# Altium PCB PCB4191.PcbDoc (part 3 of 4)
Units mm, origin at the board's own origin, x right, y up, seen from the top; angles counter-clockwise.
Board outline 160 x 160 mm, 6 copper layers (Top Layer, IM1 RIS, IM2 Signal, IM3 Signal, IM4 GND, Bottom Layer), stack 1.582 mm thick; 143 components, 121 nets, 430 pads, 4983 vias.
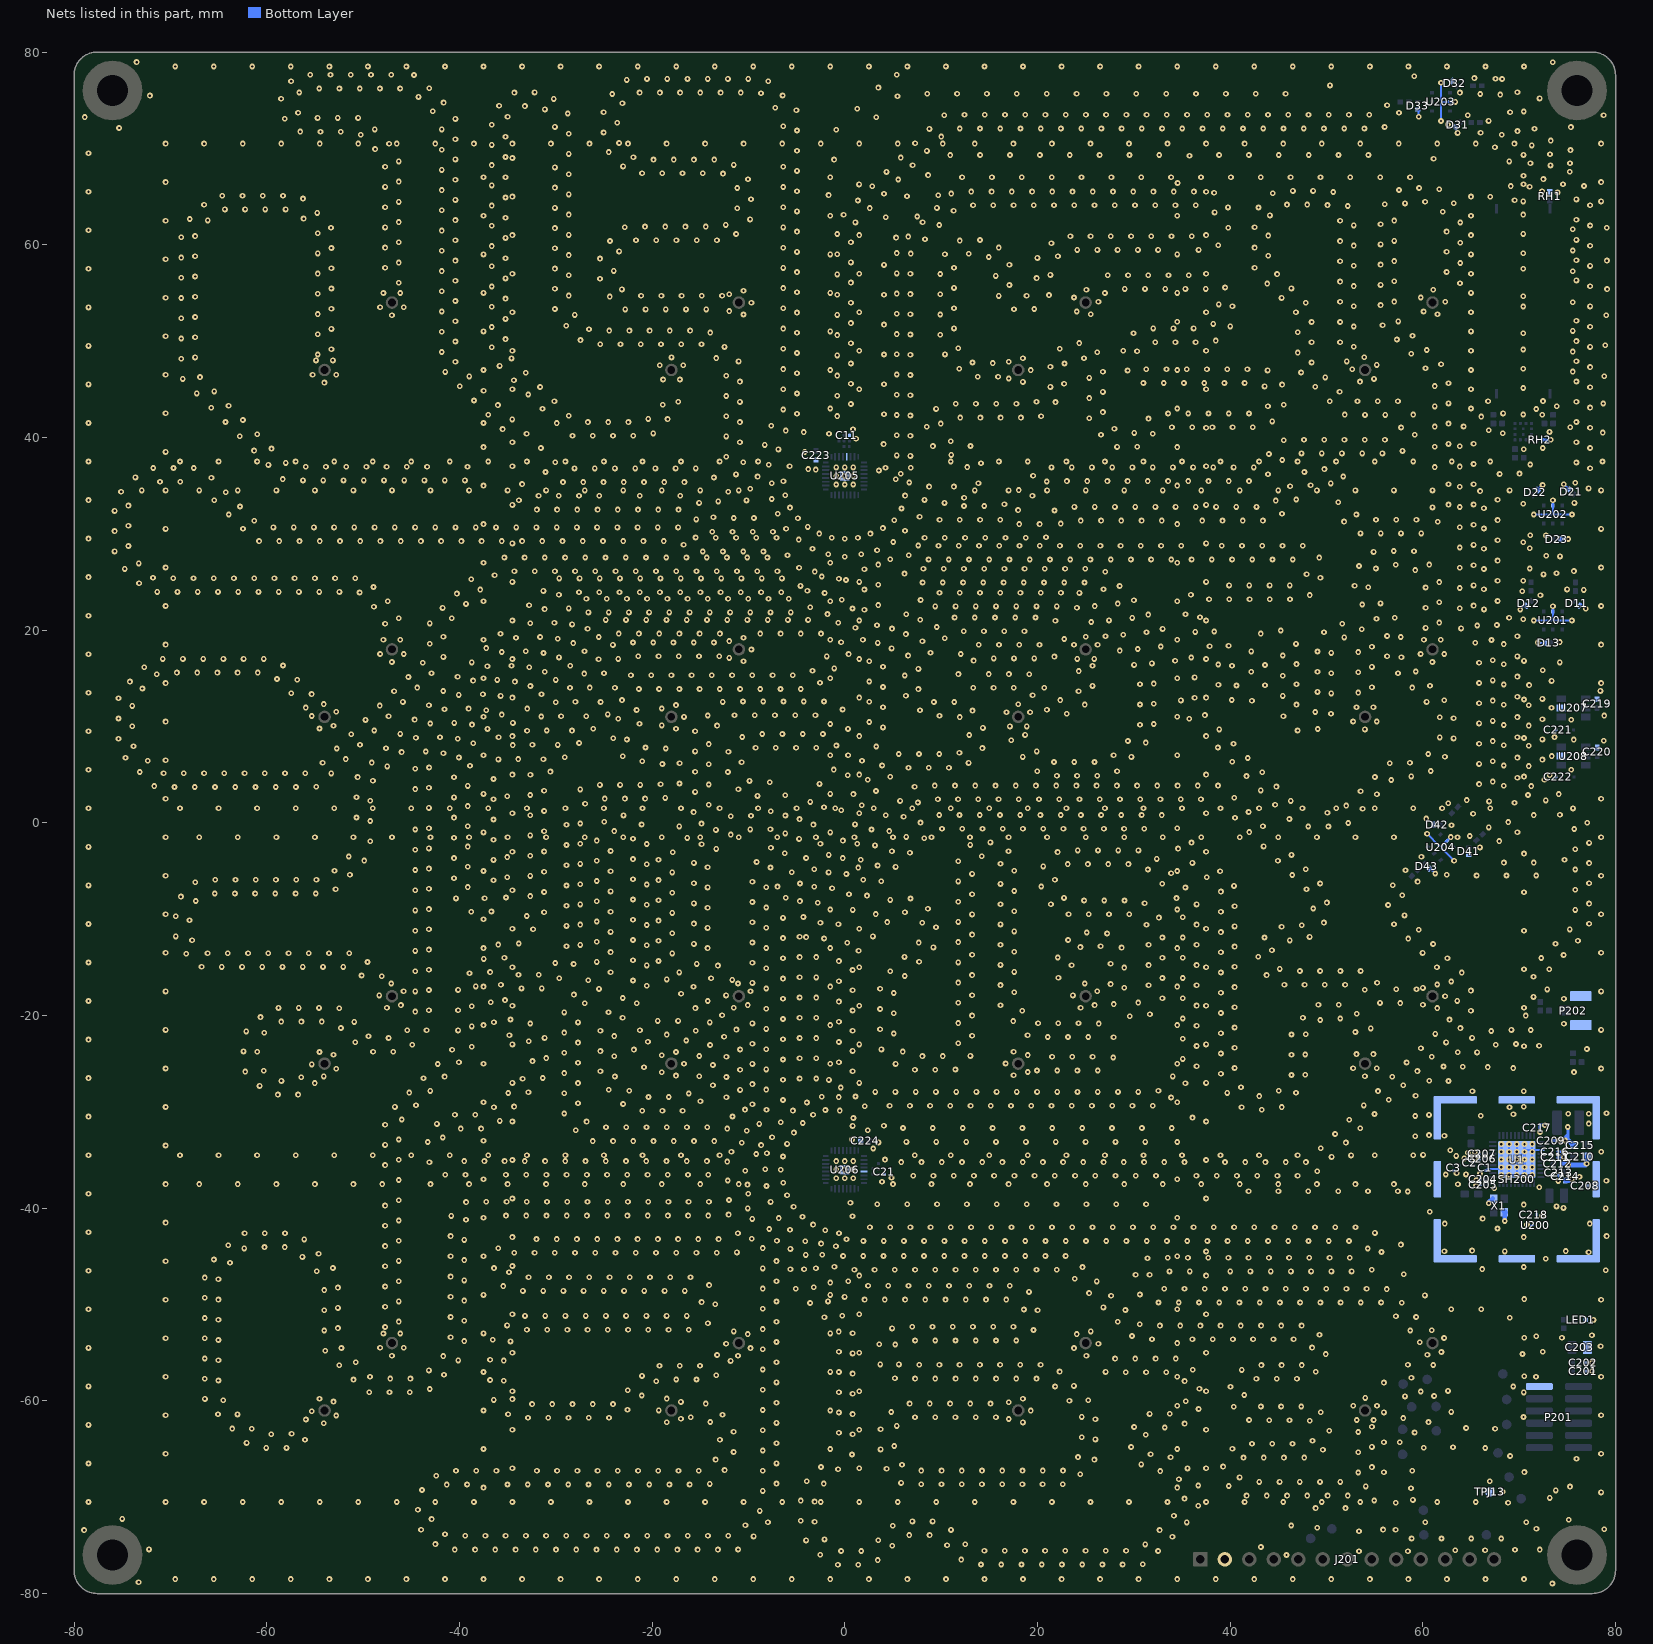
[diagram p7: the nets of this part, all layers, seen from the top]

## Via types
v1: diameter 0.6, hole 0.25, IM4 GND to Bottom Layer, tented bottom, 3953 vias
v2: diameter 0.6, hole 0.25, Top Layer to Bottom Layer, tented both sides, 851 vias
v3: diameter 0.6, hole 0.25, IM4 GND to Bottom Layer, tented both sides, 179 vias

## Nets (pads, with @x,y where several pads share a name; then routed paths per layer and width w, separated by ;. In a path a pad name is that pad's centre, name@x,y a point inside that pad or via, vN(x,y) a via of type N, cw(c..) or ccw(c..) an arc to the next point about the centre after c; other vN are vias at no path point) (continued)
GND: (continued)
  other v1: -0.714,-77.012 1.386,-77.012 14.137,-76.987 16.237,-76.987 18.337,-76.987 20.437,-76.987 22.537,-76.987 24.637,-76.987 26.737,-76.987 28.837,-76.987 30.937,-76.965 3.43,-76.528 12.099,-76.481 45.849,-76 -2.537,-75.97 58.449,-75.616 -0.388,-75.588 1.712,-75.588 32.521,-75.587 53.368,-75.606 14.494,-75.563 16.594,-75.563 18.694,-75.563 20.794,-75.563 22.894,-75.563 24.994,-75.563 27.094,-75.563 29.194,-75.563 63.363,-75.515 66.463,-75.515 -40.474,-75.437 -38.374,-75.437 -36.274,-75.437 -34.174,-75.437 -32.074,-75.437 -29.974,-75.437 -27.874,-75.437 -25.774,-75.437 -23.674,-75.437 -21.574,-75.437 -19.474,-75.437 -17.374,-75.437 -15.274,-75.437 -13.174,-75.437 69.562,-75.45 -11.074,-75.427 43.186,-75.174 4.915,-75.043 10.614,-74.996 31.188,-74.905 12.509,-74.877 -42.494,-74.863 -4.022,-74.486 3.483,-74.459 -2.109,-74.384 58.833,-74.286 61.933,-74.286 65.033,-74.286 68.133,-74.286 34.006,-74.102 -9.468,-74.075 -39.404,-74.013 -37.304,-74.013 -35.204,-74.013 -33.104,-74.013 -31.004,-74.013 -28.904,-74.013 -26.804,-74.013 -24.704,-74.013 -22.604,-74.013 -20.504,-74.013 -18.404,-74.013 -16.304,-74.013 -14.204,-74.013 -12.104,-74.013 6.7,-73.937 8.8,-73.937 -41.497,-73.845 53.375,-73.529 32.673,-73.42 -43.979,-73.378 11.024,-73.392 55.873,-73.366 71.783,-73.287 49.049,-73.166 4.968,-72.974 46.351,-72.941 -10.317,-72.91 35.491,-72.617 -7.983,-72.59 70.733,-72.597 -3.138,-72.553 7.017,-72.513 9.117,-72.513 -4.562,-72.456 -42.888,-72.272 34.158,-71.935 -8.832,-71.425 -44.312,-71.305 48.87,-71.135 51.97,-71.135 36.687,-70.891 -3.138,-70.453 -4.562,-70.356 54.966,-70.339 35.263,-70.149 41.709,-69.837 43.809,-69.837 45.909,-69.837 48.009,-69.837 50.109,-69.837 52.209,-69.837 -8.512,-69.349 -43.882,-69.249 58.768,-69.061 54.078,-68.88 39.86,-68.842 36.687,-68.791 -41.306,-68.689 -39.206,-68.687 -35.006,-68.687 -32.906,-68.687 -30.806,-68.687 -28.706,-68.687 -26.606,-68.687 -24.506,-68.687 -22.406,-68.687 -20.306,-68.687 -18.206,-68.687 -16.106,-68.687 7.934,-68.662 10.034,-68.662 12.134,-68.662 14.234,-68.662 16.334,-68.662 18.434,-68.662 20.534,-68.662 22.634,-68.662 -14.007,-68.623 -7.088,-68.59 -2.178,-68.585 5.839,-68.516 43.029,-68.413 45.129,-68.413 47.229,-68.413 49.329,-68.413 51.429,-68.413 -3.954,-68.346 34.675,-68.133 40.981,-67.949 -42.397,-67.765 24.45,-67.608 53.288,-67.435 55.96,-67.403 32.753,-67.287 -40.358,-67.263 -38.258,-67.263 -36.158,-67.263 -31.958,-67.263 -29.858,-67.263 -27.758,-67.263 -25.658,-67.263 -23.558,-67.263 -21.458,-67.263 -19.358,-67.263 -17.258,-67.263 -15.158,-67.263 -8.512,-67.249 7.946,-67.238 10.046,-67.238 12.146,-67.238 14.246,-67.238 16.346,-67.238 18.446,-67.238 20.546,-67.238 22.646,-67.238 -12.477,-67.185 -0.693,-67.101 4.339,-67.046 35.57,-67.013 54.712,-66.878 -2.469,-66.862 39.263,-66.829 5.936,-66.629 30.769,-66.601 -7.088,-66.49 -13.408,-66.101 25.908,-66.097 41.382,-65.887 43.482,-65.887 45.582,-65.887 47.682,-65.887 33.813,-65.863 24.208,-65.834 0.746,-65.571 31.736,-65.554 53.288,-65.335 -11.538,-65.306 -8.512,-65.149 49.622,-65.085 3.713,-65.042 40.229,-64.964 -60.053,-64.887 -57.953,-64.887 29.713,-64.786 54.712,-64.778 5.137,-64.687 42.268,-64.463 44.368,-64.463 46.468,-64.463 -7.088,-64.39 -62.088,-64.369 55.96,-64.303 48.544,-64.148 -56.032,-64.039 -12.962,-64.049 26.012,-63.999 24.588,-63.769 31.246,-63.512 0.812,-63.472 -59.524,-63.463 -57.424,-63.417 -0.612,-63.31 53.288,-63.235 -11.538,-63.206 50.287,-63.093 -8.512,-63.049 3.713,-62.942 -61.546,-62.897 -63.573,-62.884 33.207,-62.762 30.033,-62.71 54.712,-62.678 5.382,-62.601 35.269,-62.363 -54.082,-62.32 -7.088,-62.29 18.484,-62.237 -18.484,-62.213 -13.958,-62.2 48.26,-62.068 44.061,-62.012 46.161,-62.012 41.961,-61.99 53.137,-61.991 54.887,-61.991 -55.939,-61.932 26.012,-61.899 17.009,-61.887 -17.009,-61.863 -32.879,-61.762 -30.779,-61.762 -28.679,-61.762 -26.579,-61.762 -24.479,-61.762 -16,-61.712 7.284,-61.712 9.384,-61.712 11.484,-61.712 13.584,-61.712 15.684,-61.712 24.588,-61.669 -52.792,-61.524 -12.691,-61.452 -65.058,-61.399 -63.031,-61.412 -34.945,-61.387 0.812,-61.372 31.633,-61.351 33.733,-61.338 -0.612,-61.21 49.398,-61.191 55.96,-61.203 4.814,-61.154 -55.32,-61.082 19.309,-61.012 -19.309,-60.988 -22.55,-60.932 -8.512,-60.949 36.724,-60.849 40.378,-60.61 43.186,-60.588 45.286,-60.588 47.386,-60.588 52.787,-60.516 55.237,-60.516 -32.462,-60.338 -30.362,-60.338 -28.262,-60.338 -26.162,-60.338 -24.062,-60.338 -14.439,-60.288 6.727,-60.288 8.827,-60.288 10.927,-60.288 13.027,-60.288 15.127,-60.288 -7.088,-60.19 17.009,-60.137 -17.009,-60.113 -53.075,-60.075 35.388,-60.044 23.316,-59.998 -64.516,-59.927 25.268,-59.936 -36.43,-59.902 -34.497,-59.821 -66.422,-59.803 -54.524,-59.792 -18.484,-59.763 18.484,-59.787 54.012,-59.691 -21.065,-59.448 41.462,-59.389 0.812,-59.272 -49.357,-59.112 -47.257,-59.112 -45.157,-59.112 -0.612,-59.11 62.615,-58.966 -22.532,-58.899 -8.512,-58.849 -43.085,-58.768 36.812,-58.751 40.038,-58.538 21.831,-58.513 23.783,-58.451 -7.088,-58.09 55.96,-58.103 -19.58,-57.963 35.265,-57.948 -35.388,-57.919 -65.013,-57.886 -36.812,-57.837 -50.99,-57.792 -17.488,-57.787 -15.388,-57.787 42.727,-57.712 44.827,-57.712 46.927,-57.712 -66.437,-57.703 -47.19,-57.688 -45.09,-57.688 7.3,-57.687 9.4,-57.687 11.5,-57.687 13.6,-57.687 15.7,-57.687 17.8,-57.687 19.9,-57.687 5.2,-57.653 58.809,-57.613 -49.28,-57.487 -21.047,-57.414 -13.335,-57.343 -41.6,-57.283 0.812,-57.172 29.173,-57.037 31.273,-57.037 33.373,-57.037 -0.612,-57.01 27.074,-56.997 48.895,-56.978 22.298,-56.966 -43.17,-56.837 41.202,-56.79 36.105,-56.773 -8.512,-56.749 -19.229,-56.363 -17.129,-56.363 -15.029,-56.363 -52.475,-56.307 43.241,-56.288 45.341,-56.288 47.441,-56.288 7.719,-56.263 9.819,-56.263 11.919,-56.263 14.019,-56.263 16.119,-56.263 18.219,-56.263 20.319,-56.263 58.453,-56.26 61.069,-56.279 3.671,-56.213 5.62,-56.213 -50.765,-56.003 -7.088,-55.99 -11.85,-55.858 -35.388,-55.819 -65.013,-55.786 -40.115,-55.798 -36.812,-55.737 -66.437,-55.603 28.055,-55.613 30.155,-55.613 32.255,-55.613 34.355,-55.613 -41.685,-55.352 -11.082,-55.32 25.082,-55.32 -47.012,-55.309 -13.252,-55.244 60.476,-55.208 49.924,-55.147 0.812,-55.072 61.925,-54.925 -0.612,-54.91 -53.934,-54.797 -8.512,-54.649 -52.25,-54.518 -9.792,-54.524 23.792,-54.524 -48.237,-54.484 -45.787,-54.484 48.499,-54.474 5.234,-54.149 3.588,-54.115 -12.32,-54.082 26.32,-54.082 59.68,-53.918 -7.088,-53.89 -34.702,-53.834 -39.488,-53.794 7.293,-53.737 9.393,-53.737 11.493,-53.737 13.593,-53.737 15.693,-53.737 17.793,-53.737 -65.013,-53.686 -36.538,-53.655 31.884,-53.612 36.084,-53.612 38.184,-53.612 40.284,-53.612 42.384,-53.612 44.484,-53.612 46.584,-53.612 -66.437,-53.503 62.208,-53.476 74.438,-53.46 -40.912,-53.4 71.78,-53.303 29.812,-53.27 49.277,-53.149 -10.075,-53.075 24.075,-53.075 -47.887,-53.009 -46.137,-53.009 0.812,-52.972 -0.634,-52.81 -11.524,-52.792 25.524,-52.792 -54.037,-52.699 58.69,-52.697 60.918,-52.68 19.587,-52.645 -32.994,-52.612 -30.894,-52.612 -28.794,-52.612 -26.694,-52.612 -24.594,-52.612 -22.494,-52.612 -20.394,-52.612 -18.294,-52.612 -16.194,-52.612 -8.512,-52.549 4.907,-52.481 -52.613,-52.449 -47.712,-52.334 7,-52.313 9.1,-52.313 11.2,-52.313 13.3,-52.313 15.4,-52.313 17.5,-52.313 -35.053,-52.17 32.71,-52.188 34.81,-52.188 36.91,-52.188 39.01,-52.188 41.11,-52.188 43.21,-52.188 45.31,-52.188 47.41,-52.188 30.614,-52.057 -14.205,-51.938 -7.088,-51.79 -46.288,-51.777 28.327,-51.785 -39.488,-51.694 -65.013,-51.586 -66.437,-51.403 69.031,-51.378 -2.119,-51.325 -40.912,-51.3 59.303,-51.296 57.205,-51.212 -33.197,-51.188 -31.097,-51.188 -28.997,-51.188 -26.897,-51.188 -24.797,-51.188 -22.697,-51.188 -20.597,-51.188 -18.497,-51.188 -16.397,-51.188 -0.261,-51.168 -54.037,-50.599 20.012,-50.589 29.129,-50.572 18.588,-50.516 62.958,-50.498 66.058,-50.498 -8.512,-50.449 -52.613,-50.349 26.842,-50.3 -47.712,-50.234 -13.438,-49.983 -3.604,-49.84 57.818,-49.811 32.562,-49.787 34.662,-49.787 36.762,-49.787 38.862,-49.787 40.962,-49.787 43.062,-49.787 45.162,-49.787 47.262,-49.787 49.362,-49.787 51.462,-49.787 53.562,-49.787 55.662,-49.787 -14.862,-49.754 -7.088,-49.69 -1.746,-49.683 -46.288,-49.677 -39.488,-49.594 -65.013,-49.486 2.057,-49.487 4.157,-49.487 6.257,-49.487 8.357,-49.487 10.457,-49.487 12.557,-49.487 14.657,-49.487 16.757,-49.487 -66.437,-49.303 -40.912,-49.2 -0.024,-49.208 27.644,-49.087 60.212,-49.06 30.631,-48.963 25.357,-48.815 19.12,-48.688 -33.408,-48.587 -31.308,-48.587 -29.208,-48.587 -27.108,-48.587 -25.008,-48.587 -22.908,-48.587 -20.808,-48.587 -18.708,-48.587 -16.608,-48.587 -54.037,-48.499 56.263,-48.4 33.163,-48.363 35.263,-48.363 37.363,-48.363 39.463,-48.363 41.563,-48.363 43.663,-48.363 45.763,-48.363 47.863,-48.363 49.963,-48.363 52.063,-48.363 54.163,-48.363 -8.512,-48.349 -5.089,-48.355 -52.613,-48.249 -3.231,-48.198 -47.712,-48.134 -35.447,-48.085 2.415,-48.063 4.515,-48.063 6.615,-48.063 8.715,-48.063 10.815,-48.063 12.915,-48.063 15.015,-48.063 17.115,-48.063 -14.083,-47.984 -1.509,-47.723 26.159,-47.602 -46.288,-47.577 -7.088,-47.59 0.37,-47.588 -39.488,-47.494 -65.013,-47.386 23.873,-47.33 -66.437,-47.203 -32.816,-47.163 -30.716,-47.163 -28.616,-47.163 -26.516,-47.163 -24.416,-47.163 -22.316,-47.163 -20.216,-47.163 -18.116,-47.163 -16.016,-47.163 -40.912,-47.1 30.188,-46.91 31.636,-46.922 58.02,-46.868 -34.855,-46.662 33.705,-46.562 35.805,-46.562 40.005,-46.562 42.105,-46.562 44.205,-46.562 46.305,-46.562 48.405,-46.562 50.505,-46.562 52.605,-46.562 -54.811,-46.547 0.996,-46.387 3.096,-46.387 5.196,-46.387 7.296,-46.387 9.396,-46.387 11.496,-46.387 13.596,-46.387 15.696,-46.387 17.796,-46.387 19.896,-46.387 21.996,-46.387 54.698,-46.391 -5.649,-46.331 -4.224,-46.347 -8.512,-46.249 -2.994,-46.238 -53.129,-46.214 -36.412,-46.22 24.674,-46.117 -1.081,-46.076 -47.712,-46.034 -63.809,-45.666 -7.088,-45.49 -46.288,-45.477 -39.488,-45.394 -65.487,-45.33 72.752,-45.249 31.418,-45.208 33.517,-45.138 35.617,-45.138 37.717,-45.138 39.817,-45.138 41.917,-45.138 44.017,-45.138 46.117,-45.138 48.217,-45.138 50.317,-45.138 52.417,-45.138 -56.295,-45.062 -40.912,-45 -0.18,-44.963 1.92,-44.963 4.02,-44.963 6.12,-44.963 8.22,-44.963 10.32,-44.963 12.42,-44.963 14.52,-44.963 16.62,-44.963 18.72,-44.963 20.82,-44.963 22.92,-44.963 -4.05,-44.85 -2.35,-44.825 -54.614,-44.729 -34.3,-44.637 -32.2,-44.637 -30.1,-44.637 -28,-44.637 -25.9,-44.637 -23.8,-44.637 -21.7,-44.637 -19.6,-44.637 -17.5,-44.637 -15.4,-44.637 -13.3,-44.637 -11.2,-44.595 55.712,-44.553 -5.649,-44.231 -62.324,-44.181 -35.973,-44.166 54.288,-44.184 -8.512,-44.149 -60.229,-44.037 -58.129,-44.037 -0.925,-43.95 -47.712,-43.934 -64.002,-43.845 57.727,-43.782 1.935,-43.412 4.035,-43.412 6.135,-43.412 8.235,-43.412 10.335,-43.412 12.435,-43.412 14.535,-43.412 16.635,-43.412 18.735,-43.412 20.835,-43.412 22.935,-43.412 25.035,-43.412 27.135,-43.412 29.235,-43.412 31.335,-43.412 33.435,-43.412 35.535,-43.412 37.635,-43.412 39.735,-43.412 41.835,-43.412 43.935,-43.412 46.035,-43.412 48.135,-43.412 50.235,-43.412 52.335,-43.412 -7.046,-43.391 -46.288,-43.377 -39.488,-43.294 -56.099,-43.244 -32.002,-43.213 -29.902,-43.213 -27.802,-43.213 -25.702,-43.213 -23.602,-43.213 -21.502,-43.213 -19.402,-43.213 -17.302,-43.213 -15.202,-43.213 -13.102,-43.213 0.175,-43.225 -9.655,-43.173 -40.912,-42.9 -62.302,-42.613 -60.202,-42.613 -58.102,-42.613 -11.094,-42.598 55.025,-42.568 -7.832,-42.162 67.747,-42.114 2.607,-41.988 4.707,-41.988 6.807,-41.988 8.907,-41.988 11.007,-41.988 13.107,-41.988 15.207,-41.988 17.307,-41.988 19.407,-41.988 21.507,-41.988 23.607,-41.988 25.707,-41.988 27.807,-41.988 29.907,-41.988 32.007,-41.988 34.107,-41.988 36.207,-41.988 38.307,-41.988 40.407,-41.988 42.507,-41.988 44.607,-41.988 46.707,-41.988 48.807,-41.988 50.907,-41.988 53.007,-41.988 -47.712,-41.834 -46.288,-41.277 -39.318,-41.201 -9.609,-41.113 -40.845,-40.801 -35.163,-40.768 -33.063,-40.768 -30.963,-40.768 -28.863,-40.768 -26.763,-40.768 -24.663,-40.768 -22.563,-40.768 -20.463,-40.768 -18.363,-40.768 -16.263,-40.768 -14.163,-40.768 -12.066,-40.669 60.716,-40.361 -10.068,-40.021 -47.712,-39.734 3.378,-39.594 6.478,-39.594 9.578,-39.594 12.678,-39.594 15.778,-39.594 18.878,-39.594 21.978,-39.594 25.078,-39.594 28.178,-39.594 31.278,-39.594 -39.309,-39.369 -37.209,-39.344 -35.109,-39.344 -33.009,-39.344 -30.909,-39.344 -28.809,-39.344 -26.709,-39.344 -24.609,-39.344 -22.509,-39.344 -20.409,-39.344 -18.309,-39.344 -16.209,-39.344 -14.109,-39.344 -46.288,-39.177 -12.017,-39.156 -10.02,-38.507 58.43,-38.267 41.911,-38.246 45.011,-38.246 48.111,-38.246 51.211,-38.246 54.311,-38.246 57.411,-38.246 -10.1,-37.549 -12.157,-37.126 -46.288,-37.077 7.101,-36.644 9.201,-36.644 11.301,-36.644 13.401,-36.644 15.501,-36.644 17.601,-36.644 19.701,-36.644 21.801,-36.644 23.901,-36.644 26.001,-36.644 28.101,-36.644 30.201,-36.644 32.301,-36.644 36.501,-36.644 38.601,-36.644 40.701,-36.644 42.801,-36.644 44.901,-36.644 47.001,-36.644 -41.473,-36.537 -39.373,-36.537 -35.173,-36.537 -33.073,-36.537 -30.973,-36.537 -28.873,-36.537 -26.773,-36.537 -24.673,-36.537 -22.573,-36.537 -20.473,-36.537 -18.373,-36.537 -16.273,-36.537 -14.173,-36.537 49.045,-36.162 -10.342,-36.124 -47.712,-35.534 -43.113,-35.227 5.862,-35.219 7.962,-35.219 10.062,-35.219 12.162,-35.219 14.262,-35.219 16.362,-35.219 18.462,-35.219 20.562,-35.219 22.662,-35.219 24.762,-35.219 26.862,-35.219 28.962,-35.219 31.062,-35.219 33.162,-35.219 35.262,-35.219 39.462,-35.219 41.562,-35.219 43.662,-35.219 45.762,-35.219 47.862,-35.219 -12.21,-35.166 -39.51,-35.113 -37.41,-35.113 -35.31,-35.113 -33.21,-35.113 -31.11,-35.113 -29.01,-35.113 -26.91,-35.113 -24.81,-35.113 -22.71,-35.113 -20.61,-35.113 -18.51,-35.113 -16.41,-35.113 -14.31,-35.113 -46.288,-34.977 50.53,-34.677 60.022,-34.476 -11.767,-34.141 49.401,-33.791 -8.685,-33.458 -47.712,-33.434 -10.686,-33.207 3.5,-33.175 52.015,-33.193 -43.287,-33.134 6.396,-33.123 9.496,-33.123 12.596,-33.123 15.696,-33.123 18.796,-33.123 21.896,-33.123 24.996,-33.123 28.096,-33.123 31.196,-33.123 -26.154,-33.037 -24.054,-33.037 -21.954,-33.037 -19.854,-33.037 -17.754,-33.037 -15.654,-33.037 -13.554,-33.037 -46.288,-32.877 -41.736,-32.668 59.215,-32.538 60.639,-32.415 50.886,-32.306 -10.17,-31.973 -27.924,-31.908 2.391,-31.917 -39.853,-31.737 -37.753,-31.737 -12.19,-31.742 53.5,-31.708 6.038,-31.677 9.138,-31.677 12.238,-31.677 15.338,-31.677 18.438,-31.677 21.538,-31.677 24.638,-31.677 27.738,-31.677 30.838,-31.677 33.938,-31.677 -24.786,-31.613 -22.686,-31.613 -20.586,-31.613 -18.486,-31.613 -16.386,-31.613 -14.286,-31.613 4.06,-31.447 -47.712,-31.334 -42.341,-31.259 -8.875,-31.254 -26.8,-31.018 -35.81,-30.942 52.371,-30.821 -45.991,-30.798 0.89,-30.643 36.09,-30.595 -11.655,-30.488 59.215,-30.438 66.011,-30.408 -40.467,-30.313 -38.367,-30.313 60.639,-30.315 54.985,-30.223 -29.112,-30.177 -21.033,-29.887 -18.933,-29.887 -16.833,-29.887 -8.126,-29.795 -10.36,-29.769 43.269,-29.787 -36.416,-29.534 41.187,-29.519 -46.701,-29.494 45.351,-29.507 -34.325,-29.457 4.654,-29.362 6.754,-29.362 8.854,-29.362 10.954,-29.362 13.054,-29.362 15.154,-29.362 17.254,-29.362 19.354,-29.362 21.454,-29.362 23.554,-29.362 25.654,-29.362 27.754,-29.362 29.854,-29.362 31.954,-29.362 53.856,-29.337 -44.506,-29.313 -9.587,-29.223 -23.015,-29.192 -27.688,-29.114 -14.984,-28.892 -6.413,-28.769 56.47,-28.738 33.873,-28.509 -12.287,-28.486 -20.373,-28.463 -18.273,-28.463 1.111,-28.407 43.014,-28.363 59.251,-28.338 -58.844,-28.212 -56.744,-28.212 -16.205,-28.097 -29.112,-28.077 -34.931,-28.049 39.702,-28.034 46.836,-28.022 -45.216,-28.009 -32.84,-27.972 3.158,-27.938 5.258,-27.938 7.358,-27.938 9.458,-27.938 11.558,-27.938 13.658,-27.938 15.758,-27.938 17.858,-27.938 19.958,-27.938 22.058,-27.938 24.158,-27.938 26.258,-27.938 28.358,-27.938 30.458,-27.938 65.141,-27.87 55.341,-27.852 -43.021,-27.828 -22.372,-27.821 32.554,-27.813 45.039,-27.804 -24.5,-27.707 -10.863,-27.73 -8.163,-27.695 -0.424,-27.479 41.126,-27.444 -60.743,-27.314 57.955,-27.253 -13.688,-27.24 -9.587,-27.123 -55.014,-27.022 35.358,-27.024 -27.688,-27.014 62.658,-26.799 -58.481,-26.788 60.661,-26.782 -6.413,-26.669 -1.645,-26.686 -33.447,-26.564 -2.962,-26.544 -43.731,-26.524 -4.687,-26.537 -31.355,-26.487 -56.416,-26.408 -12.287,-26.386 56.826,-26.367 -41.536,-26.343 -23.857,-26.336 -54.082,-26.32 34.039,-26.329 -15.112,-26.304 53.988,-26.309 -17.516,-26.237 17.516,-26.213 46.363,-26.174 47.787,-26.15 39.038,-26.042 -29.112,-25.977 -18.991,-25.887 75.686,-25.879 18.991,-25.863 -62.223,-25.825 -25.362,-25.793 0.812,-25.782 59.439,-25.768 -60.302,-25.741 19.947,-25.712 22.047,-25.712 24.147,-25.712 26.247,-25.712 -10.863,-25.63 7.28,-25.637 9.38,-25.637 11.48,-25.607 -8.163,-25.595 -52.792,-25.524 52.763,-25.484 55.213,-25.484 40.462,-25.451 69.39,-25.458 -20.843,-25.364 66.726,-25.36 62.146,-25.297 64.143,-25.315 36.512,-25.27 -13.688,-25.14 -55.32,-25.082 -42.246,-25.039 -9.587,-25.023 5.27,-25.028 -16.691,-25.012 16.691,-24.988 -27.688,-24.914 58.311,-24.882 -40.051,-24.858 -0.612,-24.857 -32.412,-24.737 -6.413,-24.569 35.088,-24.509 -4.687,-24.437 -2.962,-24.444 -30.988,-24.42 27.856,-24.363 -12.287,-24.286 21.517,-24.288 23.617,-24.288 25.717,-24.288 60.924,-24.283 -23.938,-24.237 -15.112,-24.204 8.059,-24.213 10.159,-24.213 13.039,-24.2 -18.991,-24.137 18.991,-24.113 -53.075,-24.075 46.363,-24.074 47.787,-24.05 53.113,-24.009 54.863,-24.009 39.038,-23.942 -29.112,-23.877 65.628,-23.83 63.631,-23.812 -54.524,-23.792 -17.516,-23.787 -60.988,-23.756 -48.962,-23.762 -46.862,-23.762 6.01,-23.752 17.516,-23.763 -62.412,-23.733 -25.362,-23.693 0.812,-23.682 -40.761,-23.554 -21.887,-23.542 -10.863,-23.53 3.803,-23.526 -8.163,-23.495 59.796,-23.397 40.462,-23.351 -38.715,-23.238 36.512,-23.17 -13.982,-23.061 67.573,-23.037 -44.895,-23.027 69.671,-22.958 -9.587,-22.923 11.788,-22.887 -27.688,-22.814 -50.821,-22.786 62.409,-22.798 -0.612,-22.757 -20.44,-22.722 -32.808,-22.674 -16.462,-22.595 -6.413,-22.469 35.088,-22.409 -47.35,-22.338 -31.159,-22.327 -4.687,-22.337 -2.962,-22.344 65.116,-22.327 27.905,-22.264 21.064,-22.237 23.164,-22.237 25.264,-22.237 -12.532,-22.2 -49.442,-22.151 -23.938,-22.137 13.212,-22.107 -34.815,-22.054 18.971,-22.062 -18.472,-21.987 46.363,-21.974 47.856,-21.951 61.281,-21.912 5.087,-21.866 39.038,-21.842 -60.256,-21.788 -29.112,-21.777 53.003,-21.71 -62.134,-21.652 67.091,-21.613 -25.362,-21.593 -15.467,-21.576 0.812,-21.582 -43.41,-21.542 -40.137,-21.549 -21.268,-21.535 -45.412,-21.529 69.188,-21.498 71.191,-21.509 -11.252,-21.466 3.663,-21.431 -8.163,-21.395 54.599,-21.339 63.894,-21.313 -52.306,-21.301 40.462,-21.251 -38.713,-21.138 36.512,-21.07 -32.638,-20.835 -9.587,-20.823 26.361,-20.84 20.061,-20.813 22.161,-20.813 24.261,-20.813 11.788,-20.787 -36.425,-20.707 -27.688,-20.714 -14.017,-20.715 -50.927,-20.666 -0.612,-20.657 -58.499,-20.637 -56.399,-20.637 -54.299,-20.637 17.478,-20.585 -19.407,-20.563 -17.307,-20.563 49.341,-20.466 -34.697,-20.421 62.766,-20.427 -6.413,-20.369 35.088,-20.309 51.436,-20.312 -2.962,-20.244 47.551,-20.242 -23.068,-20.226 -4.687,-20.237 -60.649,-20.167 29.58,-20.087 70.672,-20.013 13.212,-20.007 -12.737,-19.981 31.668,-19.864 53.138,-19.831 5.087,-19.766 39.038,-19.742 -29.112,-19.677 -24.524,-19.667 -44.587,-19.598 18.415,-19.508 64.987,-19.52 0.812,-19.482 -43.163,-19.457 -40.137,-19.449 3.663,-19.331 -8.163,-19.295 -52.479,-19.252 -15.502,-19.23 61.484,-19.237 -58.779,-19.213 -56.679,-19.213 -54.579,-19.213 -47.524,-19.208 -11.524,-19.208 24.476,-19.208 40.462,-19.151 -38.713,-19.038 36.512,-18.97 16.163,-18.948 -46.075,-18.925 -10.075,-18.925 25.925,-18.925 49.162,-18.895 51.262,-18.888 60.009,-18.887 27.909,-18.816 -21.583,-18.741 -26.998,-18.731 55.555,-18.693 57.655,-18.712 11.788,-18.687 30.45,-18.663 -36.737,-18.63 -0.612,-18.557 -14.221,-18.496 63.563,-18.484 -35.268,-18.4 -6.413,-18.269 32.962,-18.21 35.088,-18.209 -23.04,-18.182 -4.687,-18.137 -2.962,-18.144 71.483,-18.075 62.309,-18.012 -48.32,-17.918 -12.32,-17.918 13.212,-17.907 23.68,-17.918 -28.112,-17.83 -16.987,-17.745 5.087,-17.666 39.038,-17.642 17.587,-17.578 -44.587,-17.498 -45.792,-17.476 -9.792,-17.476 26.208,-17.476 64.987,-17.42 0.812,-17.382 -43.163,-17.357 -40.137,-17.349 53.965,-17.322 72.908,-17.294 57.238,-17.288 59.338,-17.288 -25.513,-17.246 3.663,-17.231 -8.163,-17.195 -33.554,-17.187 -31.454,-17.187 29.012,-17.132 60.009,-17.137 40.462,-17.051 -15.706,-17.011 -38.297,-16.979 -20.563,-16.906 31.538,-16.866 36.512,-16.87 16.163,-16.848 45.627,-16.812 47.727,-16.812 49.827,-16.812 51.927,-16.812 -35.692,-16.809 61.484,-16.787 27.588,-16.741 -47.082,-16.68 -11.082,-16.68 24.918,-16.68 -9.587,-16.623 11.788,-16.587 55.255,-16.597 -0.612,-16.457 62.945,-16.477 -21.987,-16.365 -26.627,-16.345 -11.689,-16.304 -18.472,-16.26 -6.413,-16.169 -29.633,-16.141 -13.877,-16.13 32.962,-16.11 35.088,-16.109 22.171,-16.078 -4.687,-16.037 -2.962,-16.044 71.483,-15.975 -48.059,-15.934 6.229,-15.903 -50.157,-15.85 13.212,-15.807 43.781,-15.813 -33.871,-15.763 -31.771,-15.763 -38.949,-15.617 39.038,-15.542 64.032,-15.55 -24.313,-15.523 -17.191,-15.526 -36.812,-15.495 17.587,-15.478 -44.587,-15.398 4.708,-15.409 47.238,-15.388 49.338,-15.388 51.438,-15.388 53.538,-15.388 0.812,-15.282 -43.163,-15.257 73.127,-15.206 45.15,-15.167 -8.163,-15.095 29.012,-15.032 61.46,-14.992 -64.661,-14.962 -62.561,-14.962 -60.461,-14.962 -58.361,-14.962 -56.261,-14.962 -54.161,-14.962 -52.061,-14.962 -66.76,-14.95 40.462,-14.951 -20.563,-14.806 -13.174,-14.819 23.537,-14.789 31.538,-14.766 36.512,-14.77 16.163,-14.748 -28.148,-14.656 -15.362,-14.645 27.588,-14.641 -30.057,-14.549 -9.587,-14.523 11.788,-14.487 -49.544,-14.449 -25.737,-14.443 7.714,-14.418 -19.337,-14.347 -0.612,-14.357 -21.987,-14.265 -37.464,-14.132 -6.413,-14.069 62.547,-14.065 72.284,-14.034 -35.327,-14.01 32.962,-14.01 35.088,-14.009 22.113,-13.979 -2.962,-13.944 -4.687,-13.937 6.193,-13.924 42.913,-13.901 74.612,-13.721 13.212,-13.707 -68.364,-13.594 -66.136,-13.538 -64.036,-13.538 -61.936,-13.538 -59.836,-13.538 -57.736,-13.538 -55.636,-13.538 -53.536,-13.538 -51.436,-13.538 -17.913,-13.554 59.975,-13.507 39.038,-13.442 -24.313,-13.423 17.587,-13.378 -44.587,-13.298 1.432,-13.275 44.337,-13.231 -43.163,-13.157 -14.238,-13.008 -8.163,-12.995 28.733,-12.951 9.199,-12.934 24.457,-12.901 40.462,-12.851 -28.887,-12.805 26.555,-12.812 -20.563,-12.706 -27.463,-12.671 36.512,-12.67 -35.98,-12.647 16.163,-12.648 31.538,-12.666 61.062,-12.58 -15.662,-12.567 73.769,-12.549 -33.842,-12.525 0.25,-12.443 -9.587,-12.423 7.678,-12.44 11.788,-12.387 -25.737,-12.343 -19.337,-12.247 76.097,-12.236 -67.749,-12.193 46.174,-12.212 -21.987,-12.165 23.175,-12.167 58.49,-12.022 -2.15,-12.008 -6.413,-11.969 32.962,-11.91 35.088,-11.909 43.564,-11.904 -4.018,-11.861 -4.687,-11.837 48.241,-11.842 -69.437,-11.789 2.917,-11.79 13.212,-11.607 27.223,-11.492 -17.913,-11.454 25.125,-11.388 39.038,-11.342 -24.313,-11.323 17.587,-11.278 -44.587,-11.198 59.577,-11.095 -43.163,-11.057 75.254,-11.064 -32.357,-11.04 -14.238,-10.908 -8.163,-10.895 9.462,-10.85 45.342,-10.788 40.462,-10.751 -28.887,-10.705 47.437,-10.631 -20.563,-10.606 -27.463,-10.571 31.32,-10.577 36.512,-10.57 16.163,-10.548 57.005,-10.537 -0.665,-10.523 -15.662,-10.467 77.253,-10.483 -2.533,-10.376 8.038,-10.371 49.726,-10.357 -9.587,-10.323 4.402,-10.305 11.788,-10.287 -25.737,-10.243 -19.337,-10.147 -68.013,-10.11 -21.987,-10.065 -6.413,-9.869 32.599,-9.842 35.088,-9.809 -4.292,-9.774 -69.437,-9.689 -33.01,-9.677 58.092,-9.61 13.212,-9.507 3.22,-9.473 23.225,-9.487 25.325,-9.487 27.425,-9.487 29.525,-9.487 -17.913,-9.354 -31.213,-9.279 6.239,-9.287 39.038,-9.242 -38.776,-9.237 -24.313,-9.223 -36.677,-9.206 17.587,-9.178 -44.587,-9.098 0.82,-9.038 75.829,-9.044 -43.163,-8.957 8.63,-8.922 48.613,-8.891 -14.238,-8.808 -8.163,-8.795 40.462,-8.651 -28.887,-8.605 56.388,-8.53 -20.563,-8.506 -27.463,-8.471 21.397,-8.454 36.512,-8.47 16.163,-8.448 77.253,-8.383 -15.662,-8.367 31.114,-8.357 -2.807,-8.289 50.037,-8.28 -9.587,-8.223 11.788,-8.187 -25.737,-8.143 -4.656,-8.124 -67.357,-8.115 24.835,-8.063 26.935,-8.063 29.035,-8.063 -19.337,-8.047 4.721,-8.004 -21.987,-7.965 -40.355,-7.852 6.817,-7.863 -37.392,-7.838 22.752,-7.795 34.432,-7.814 -6.131,-7.788 -35.161,-7.752 -68.913,-7.656 -32.637,-7.611 2.304,-7.553 57.862,-7.523 0.437,-7.406 13.212,-7.407 -65.407,-7.337 -63.307,-7.337 -61.207,-7.337 -59.107,-7.337 -57.007,-7.337 -54.907,-7.337 -17.913,-7.254 -31.213,-7.179 39.038,-7.142 -24.313,-7.123 17.587,-7.078 -44.587,-6.998 75.829,-6.944 47.925,-6.907 -52.855,-6.889 -43.163,-6.857 -1.322,-6.804 -14.238,-6.708 35.352,-6.72 -8.163,-6.695 -39.138,-6.67 -6.983,-6.625 -3.171,-6.639 20.388,-6.613 40.396,-6.553 -28.887,-6.505 56.881,-6.489 -20.563,-6.406 -27.463,-6.371 16.163,-6.348 32.947,-6.329 -4.646,-6.303 49.334,-6.301 77.253,-6.283 -15.662,-6.267 -67.428,-6.171 -9.587,-6.123 59.45,-6.1 3.789,-6.068 11.788,-6.087 -25.737,-6.043 -36.462,-5.955 -19.337,-5.947 1.922,-5.921 21.812,-5.917 -65.344,-5.913 -63.244,-5.913 -61.144,-5.913 -59.044,-5.913 -56.944,-5.913 -54.844,-5.913 -21.987,-5.865 -40.562,-5.762 -35.038,-5.655 37.564,-5.646 -32.637,-5.511 65.581,-5.469 68.681,-5.469 71.781,-5.469 46.44,-5.422 -51.37,-5.404 62.482,-5.384 0.163,-5.319 13.212,-5.307 33.867,-5.235 -17.913,-5.154 -1.686,-5.154 -5.498,-5.14 -31.213,-5.079 -24.313,-5.023 38.956,-5.024 -52.962,-4.981 17.587,-4.978 58.2,-4.925 -44.587,-4.898 31.462,-4.844 75.829,-4.844 -3.161,-4.819 47.849,-4.816 -43.163,-4.757 -7.712,-4.644 -14.238,-4.608 -39.138,-4.57 5.274,-4.583 20.595,-4.523 3.407,-4.436 -28.887,-4.405 -20.563,-4.306 -27.463,-4.271 23.137,-4.287 25.237,-4.287 27.337,-4.287 29.437,-4.287 16.163,-4.248 -15.662,-4.167 36.079,-4.161 77.253,-4.183 68.417,-4.131 71.517,-4.131 -9.151,-4.069 11.788,-3.987 -25.737,-3.943 44.955,-3.937 -49.885,-3.919 -36.462,-3.855 -19.337,-3.847 1.648,-3.835 74.701,-3.843 -21.987,-3.765 32.382,-3.75 -40.562,-3.662 -4.013,-3.656 -0.201,-3.669 -35.038,-3.555 59.851,-3.519 -51.477,-3.496 14.215,-3.462 -32.637,-3.411 -1.676,-3.334 46.364,-3.332 -6.227,-3.159 6.759,-3.098 -17.848,-3.055 22.087,-3.044 -31.213,-2.979 4.892,-2.951 16.996,-2.963 -24.313,-2.923 24.179,-2.863 26.279,-2.863 28.379,-2.863 30.479,-2.863 -44.587,-2.798 75.829,-2.744 -13.332,-2.714 34.594,-2.676 -43.163,-2.657 -7.667,-2.584 65.925,-2.55 -39.138,-2.47 43.47,-2.452 3.133,-2.35 -28.887,-2.305 13.026,-2.291 -20.563,-2.206 -14.859,-2.227 1.284,-2.184 -27.463,-2.171 -2.528,-2.171 77.253,-2.083 35.986,-2.054 15.111,-2.038 -49.263,-1.913 67.924,-1.901 -25.737,-1.843 -0.191,-1.849 -36.462,-1.755 -4.742,-1.674 -21.987,-1.665 8.244,-1.613 -16.363,-1.57 -40.562,-1.562 6.376,-1.466 64.875,-1.375 -32.637,-1.311 -11.847,-1.229 -6.182,-1.099 69.817,-0.991 41.985,-0.968 -31.213,-0.879 4.618,-0.865 -23.926,-0.859 -13.374,-0.742 -44.587,-0.698 -9.818,-0.687 2.769,-0.699 -7.718,-0.661 75.715,-0.647 10.09,-0.612 12.19,-0.612 14.29,-0.612 16.39,-0.612 18.49,-0.612 20.59,-0.612 22.69,-0.612 24.79,-0.612 26.89,-0.612 28.99,-0.612 31.09,-0.612 -43.163,-0.557 34.501,-0.569 66.839,-0.477 48.098,-0.387 50.198,-0.387 -39.138,-0.37 -17.18,-0.372 43.394,-0.362 -28.887,-0.205 -21.094,-0.174 -3.257,-0.189 1.062,-0.164 -14.878,-0.085 -27.463,-0.071 52.265,-0.017 7.861,0.019 77.064,0.008 68.866,0.073 -24.97,0.112 -49.263,0.187 -36.462,0.345 -4.697,0.386 46.149,0.394 -40.562,0.538 40.5,0.517 -50.687,0.55 6.103,0.62 -11.834,0.686 -9.735,0.737 -22.974,0.762 -6.166,0.754 -32.637,0.789 4.254,0.786 9.806,0.812 11.906,0.812 14.006,0.812 16.106,0.812 18.206,0.812 20.306,0.812 22.406,0.812 24.506,0.812 26.606,0.812 28.706,0.812 30.806,0.812 32.906,0.796 74.23,0.837 65.215,0.928 50.09,1.037 -15.695,1.112 41.909,1.123 -7.686,1.197 -31.213,1.221 -0.362,1.301 53.75,1.468 75.584,1.498 -43.163,1.543 -2.163,1.603 -39.138,1.73 52.053,1.785 1.752,1.82 -14.113,1.87 44.664,1.879 -26.951,1.966 69.513,2.071 7.588,2.105 -3.587,2.169 66.873,2.216 -49.263,2.287 5.739,2.271 46.289,2.268 72.745,2.322 64.554,2.352 9.661,2.438 11.761,2.438 13.861,2.438 15.961,2.438 18.061,2.438 20.161,2.438 22.261,2.438 24.361,2.438 26.461,2.438 28.561,2.438 30.661,2.438 32.761,2.438 34.861,2.438 36.961,2.438 -36.462,2.445 -24.924,2.513 -22.824,2.513 -20.724,2.513 -18.625,2.58 40.424,2.608 -40.562,2.638 -50.687,2.65 -35.038,2.745 -9.056,2.788 -6.188,2.854 -32.637,2.889 70.915,2.885 55.235,2.953 0.898,2.981 74.099,2.983 -15.537,3.207 53.538,3.27 3.237,3.305 -31.213,3.321 43.179,3.364 -27.466,3.466 -11.038,3.481 -44.587,3.502 -43.163,3.643 -69.571,3.713 -67.471,3.713 -65.371,3.713 -63.271,3.713 -61.171,3.713 -59.071,3.713 -56.971,3.713 -54.871,3.738 7.244,3.735 44.804,3.753 -71.668,3.814 71.26,3.807 -39.138,3.83 9.34,3.862 11.44,3.862 13.54,3.862 15.64,3.862 17.74,3.862 19.84,3.862 21.94,3.862 24.04,3.862 26.14,3.862 28.24,3.862 30.34,3.862 32.44,3.862 34.54,3.862 36.64,3.862 38.74,3.862 68.398,3.85 -25.419,3.937 -23.319,3.937 -21.219,3.937 -14.113,3.97 -19.121,4.012 65.838,4.015 -2.623,4.034 -17.157,4.082 -7.791,4.21 67.262,4.28 -9.886,4.344 -48.976,4.367 56.72,4.438 2.383,4.465 72.614,4.468 -36.462,4.545 69.812,4.672 -50.567,4.747 -40.562,4.738 55.022,4.755 4.722,4.789 58.786,4.813 41.694,4.849 22.014,4.888 24.114,4.888 26.214,4.888 0.302,4.945 -32.629,4.989 -53.293,5.124 -70.703,5.137 -68.603,5.137 -66.503,5.137 -64.403,5.137 -62.303,5.137 -60.203,5.137 -58.103,5.137 -56.003,5.137 43.319,5.238 -73.18,5.272 -12.137,5.271 -15.537,5.307 -30.553,5.315 19.966,5.352 28.261,5.354 60.809,5.377 -1.138,5.519 -44.587,5.602 6.608,5.713 8.708,5.713 10.808,5.713 -43.15,5.743 -47.491,5.852 70.988,5.89 -38.901,5.917 3.868,5.95 68.388,5.95 -14.113,6.07 -18.936,6.103 65.838,6.115 -17.149,6.182 56.561,6.184 -54.207,6.226 12.847,6.215 58.66,6.237 -49.104,6.253 -10.713,6.274 21.717,6.312 23.817,6.312 25.917,6.312 40.209,6.333 67.262,6.38 -21.016,6.388 1.787,6.43 -72.342,6.45 -35.951,6.582 72.412,6.558 -31.282,6.6 -51.808,6.609 -33.905,6.613 41.834,6.723 -74.664,6.757 -40.056,6.776 69.812,6.772 -29.068,6.799 18.481,6.837 29.746,6.839 62.294,6.862 -23.049,6.916 0.347,7.004 27.899,7.006 5.6,7.137 7.7,7.137 9.8,7.137 60.557,7.139 -41.665,7.228 11.896,7.278 -46.006,7.337 -12.082,7.37 -43.506,7.402 -15.537,7.407 19.925,7.407 -52.722,7.711 -18.586,7.713 -47.619,7.738 14.28,7.75 -9.257,7.788 -7.157,7.788 -5.057,7.788 -2.957,7.788 -20.683,7.812 38.724,7.818 3.272,7.915 -73.827,7.934 70.988,7.99 -0.87,8.023 68.388,8.05 -34.466,8.067 -50.323,8.094 -32.42,8.098 -29.797,8.085 -14.113,8.17 40.349,8.208 65.838,8.215 -38.572,8.261 -27.583,8.284 31.231,8.324 67.262,8.48 29.384,8.491 17.288,8.565 -22.613,8.642 72.412,8.658 -40.18,8.713 -75.387,8.729 63.187,8.762 -24.037,8.769 -44.521,8.822 61.763,8.858 -42.021,8.887 -35.931,8.887 69.812,8.872 -10.651,8.907 12.913,9.115 18.712,9.122 -51.237,9.196 -46.134,9.223 -8.573,9.212 -6.473,9.212 -4.373,9.212 -2.273,9.212 -15.537,9.507 -32.981,9.552 -48.838,9.579 -28.312,9.57 47.003,9.579 -30.935,9.583 38.864,9.693 53.988,9.691 -37.087,9.746 0.337,9.741 49.097,9.739 -26.098,9.769 -17.516,9.763 -54.524,9.792 14.337,9.849 3.962,9.898 17.137,10.009 18.887,10.009 -73.963,10.03 -53.075,10.075 -13.255,10.087 -18.991,10.113 70.988,10.089 68.388,10.15 30.638,10.176 -38.695,10.198 32.062,10.253 -21.309,10.288 -43.036,10.307 65.838,10.315 -40.536,10.372 -34.446,10.371 2.538,10.467 52.763,10.516 55.213,10.516 67.262,10.58 -49.752,10.68 -44.649,10.708 72.412,10.758 35.754,10.788 -23.506,10.801 -75.387,10.829 63.187,10.862 11.924,10.968 61.763,10.958 69.812,10.972 -16.691,10.988 -31.496,11.037 -47.354,11.064 -29.45,11.068 -26.827,11.055 45.523,11.069 -55.32,11.082 9.829,11.113 -14.217,11.14 -11.452,11.163 -9.352,11.163 -7.252,11.163 -5.152,11.163 -3.052,11.163 37.379,11.178 -35.602,11.231 -24.613,11.254 23.029,11.313 50.468,11.329 16.787,11.484 19.237,11.484 48.838,11.495 -52.792,11.524 13.257,11.65 -37.21,11.683 7.809,11.684 -21.614,11.712 -0.23,11.763 20.974,11.744 -41.551,11.792 -39.051,11.857 -32.961,11.856 -18.991,11.863 -55.96,11.953 53.113,11.991 54.863,11.991 3.962,11.998 -73.963,12.13 -48.267,12.165 -43.164,12.193 70.988,12.189 -17.516,12.213 24.9,12.267 68.388,12.25 30.638,12.276 46.887,12.273 -54.082,12.32 18.012,12.309 32.062,12.353 65.838,12.415 -30.011,12.522 -45.869,12.549 -25.342,12.54 -12.661,12.55 9.254,12.537 11.354,12.537 60.393,12.55 -27.965,12.553 2.538,12.567 -10.562,12.587 -8.462,12.587 -6.362,12.587 -4.262,12.587 -2.162,12.587 42.255,12.672 34.888,12.701 67.262,12.68 62.227,12.73 -23.128,12.739 22.372,12.737 40.157,12.748 72.412,12.858 -75.387,12.929 36.312,12.987 69.812,13.072 -35.725,13.167 45.463,13.168 6.343,13.188 19.489,13.229 -40.066,13.277 -55.347,13.354 -37.566,13.342 -31.476,13.341 -57.445,13.438 50.487,13.429 53.288,13.519 49.063,13.583 -46.782,13.65 24.265,13.647 -41.68,13.678 -21.37,13.888 -19.27,13.888 -17.17,13.888 -15.07,13.888 -12.97,13.888 -10.87,13.888 -8.77,13.888 -6.67,13.888 -4.57,13.888 7.637,13.878 -72.901,13.942 -28.526,14.006 -23.858,14.025 13.341,14.024 15.441,14.013 17.541,14.013 20.71,14.022 -44.384,14.034 -26.48,14.037 58.908,14.035 54.712,14.076 3.962,14.098 -32.632,14.2 25.712,14.204 60.742,14.215 40.657,14.25 43.612,14.275 71.03,14.289 38.781,14.334 68.388,14.35 30.638,14.376 46.887,14.373 32.062,14.453 65.838,14.515 -2.575,14.543 -74.198,14.659 -34.24,14.652 2.538,14.667 73.363,14.731 -38.581,14.762 67.262,14.78 -36.081,14.826 -29.991,14.826 -56.832,14.839 -58.93,14.923 36.312,15.087 -45.297,15.135 -40.195,15.163 69.812,15.172 45.463,15.268 6.213,15.284 -22.199,15.312 -20.099,15.312 -17.999,15.312 -15.899,15.312 -13.799,15.312 -11.699,15.312 -9.599,15.312 -7.499,15.312 -5.399,15.312 19.135,15.41 -71.416,15.427 11.789,15.439 14.935,15.437 17.035,15.437 -27.041,15.491 -42.899,15.519 -24.995,15.522 57.423,15.52 50.487,15.529 -69.322,15.588 -67.222,15.588 -65.122,15.588 -63.022,15.588 -60.922,15.588 53.288,15.619 -31.147,15.685 42.188,15.688 49.063,15.683 59.258,15.7 24.288,15.747 -3.352,15.781 72.452,15.835 7.637,15.978 -1.09,16.027 -72.713,16.144 -32.755,16.137 54.712,16.176 3.962,16.198 -37.096,16.247 -34.596,16.311 -28.507,16.311 25.712,16.304 40.187,16.297 -58.317,16.324 30.031,16.386 43.612,16.375 38.763,16.434 68.388,16.45 46.887,16.473 31.877,16.544 65.838,16.615 -43.812,16.62 -38.71,16.648 74.213,16.651 -47.012,16.691 60.988,16.691 -10.516,16.763 2.538,16.767 34.281,16.812 13.373,16.84 67.262,16.88 -25.556,16.976 -70.801,17.012 -68.701,17.012 -66.601,17.012 -64.501,17.012 -62.401,17.012 -60.301,17.012 -23.51,17.007 24.137,17.009 25.887,17.009 15.461,17.063 17.561,17.063 19.661,17.063 -11.991,17.113 -29.662,17.17 35.952,17.155 57.773,17.185 -41.663,17.217 -1.867,17.266 21.752,17.254 69.812,17.272 -21.429,17.288 -19.329,17.288 -17.229,17.288 -15.129,17.288 -13.029,17.288 56.288,17.286 6.571,17.353 45.463,17.368 -48.237,17.516 -45.787,17.516 0.395,17.512 12.042,17.524 59.763,17.516 62.213,17.516 -31.27,17.622 50.487,17.629 8.893,17.661 -35.611,17.731 53.288,17.719 49.063,17.783 -33.111,17.796 -27.022,17.796 42.188,17.788 28.546,17.871 -9.691,17.988 30.397,18.035 4.856,18.099 -37.225,18.133 54.712,18.276 32.796,18.296 37.862,18.331 39.84,18.368 -24.071,18.461 13.908,18.487 16.008,18.487 18.108,18.487 20.208,18.487 23.787,18.484 26.237,18.484 68.388,18.55 -43.087,18.591 46.831,18.572 -28.177,18.655 3.417,18.674 65.441,18.677 -21.986,18.712 -19.886,18.712 -17.786,18.712 -15.686,18.712 -13.586,18.712 -0.382,18.751 74.213,18.751 8.056,18.838 -11.991,18.863 67.123,18.975 -47.887,18.991 -46.137,18.991 1.88,18.997 60.113,18.991 61.863,18.991 22.787,19.081 -29.786,19.107 10.378,19.146 -34.126,19.216 -10.516,19.213 51.838,19.238 -31.626,19.281 -25.537,19.281 25.012,19.309 57.712,19.284 -41.663,19.317 27.062,19.356 69.812,19.372 56.288,19.386 28.912,19.52 6.341,19.584 -35.74,19.618 -23.467,19.638 -21.367,19.638 -19.267,19.638 -17.167,19.638 -15.067,19.638 -12.967,19.638 -8.767,19.638 -6.667,19.638 -4.567,19.638 -2.467,19.638 43.181,19.638 31.311,19.781 49.739,19.771 36.377,19.816 38.355,19.853 12.343,19.888 14.443,19.888 16.543,19.888 18.643,19.888 45.256,19.961 53.663,20.095 -26.692,20.14 32.982,20.125 4.902,20.159 63.974,20.18 1.103,20.236 60.288,20.225 9.541,20.323 65.655,20.477 3.342,20.504 67.687,20.53 -28.301,20.592 -47.712,20.668 51.641,20.662 -43.083,20.691 -32.641,20.701 -0.689,20.754 -30.141,20.766 61.712,20.782 25.577,20.841 21.865,20.967 27.428,21.005 -24.805,21.062 -22.705,21.062 -20.605,21.062 -18.505,21.062 -16.405,21.062 -14.305,21.062 -12.205,21.062 -10.105,21.062 -8.005,21.062 -5.905,21.062 -3.805,21.062 7.826,21.068 55.191,21.177 -46.288,21.225 -40.803,21.232 29.826,21.266 68.947,21.286 11.393,21.312 13.493,21.312 15.593,21.312 17.693,21.312 19.793,21.312 57.092,21.29 36.87,21.337 31.497,21.61 6.386,21.644 -1.793,21.664 35.363,21.655 -26.61,21.838 -24.51,21.838 -22.41,21.838 -20.31,21.838 -18.21,21.838 -16.11,21.838 -14.01,21.838 -11.91,21.838 -9.81,21.838 -7.71,21.838 -5.61,21.838 2.038,22.116 66.344,22.144 -31.156,22.186 -28.656,22.251 0.796,22.239 63.838,22.275 -41.742,22.308 24.092,22.326 60.288,22.325 -3.577,22.365 -48.874,22.417 9.396,22.463 11.496,22.463 13.596,22.463 15.696,22.463 17.796,22.463 19.896,22.463 21.996,22.463 25.943,22.49 65.262,22.54 -32.77,22.587 3.462,22.601 53.706,22.662 -39.318,22.717 28.341,22.751 55.607,22.775 61.712,22.882 -47.43,22.987 67.762,23.02 30.012,23.095 7.871,23.129 -0.309,23.149 37.815,23.213 39.915,23.213 42.015,23.213 44.115,23.213 46.215,23.213 -26.816,23.262 -24.716,23.262 -22.616,23.262 -20.516,23.262 -18.416,23.262 -16.316,23.262 -14.216,23.262 -12.116,23.262 -10.016,23.262 -7.916,23.262 -5.816,23.262 72.2,23.625 48.271,23.639 -29.672,23.671 35.922,23.679 -40.257,23.793 -2.092,23.85 24.357,23.866 -50.359,23.902 9.83,23.887 11.93,23.887 14.03,23.887 16.13,23.887 18.23,23.887 20.33,23.887 22.43,23.887 -27.589,23.938 -25.489,23.938 -23.389,23.938 -21.289,23.938 -19.189,23.938 -17.089,23.938 -14.989,23.938 -12.889,23.938 -10.789,23.938 -8.689,23.938 -6.589,23.938 -71.358,23.963 -69.258,23.963 -67.158,23.963 -65.058,23.963 -62.958,23.963 -60.858,23.963 -58.758,23.963 -56.658,23.963 -54.558,23.963 -52.458,23.963 70.325,24.025 -31.285,24.072 -3.88,24.077 76.7,24.175 -37.833,24.202 2.038,24.216 26.857,24.236 74.975,24.225 66.338,24.244 63.838,24.375 60.288,24.425 54.337,24.448 -48.915,24.472 28.527,24.58 -4.593,24.593 52.913,24.606 39.89,24.637 41.99,24.637 44.09,24.637 46.19,24.637 65.262,24.64 3.462,24.701 -73.252,24.87 8.078,24.94 10.178,24.94 12.278,24.94 14.378,24.94 16.478,24.94 18.578,24.94 20.678,24.94 22.778,24.94 24.878,24.94 61.712,24.982 67.762,25.12 0.124,25.204 -38.772,25.278 -0.607,25.335 -29.628,25.362 -27.528,25.362 -25.428,25.362 -23.328,25.362 -21.228,25.362 -19.128,25.362 -17.028,25.362 -14.928,25.362 -12.828,25.362 -10.728,25.362 -8.628,25.362 -6.528,25.362 -69.705,25.387 -67.605,25.387 -65.505,25.387 -63.405,25.387 -61.305,25.387 -59.205,25.387 -57.105,25.387 -55.005,25.387 -52.905,25.387 -50.805,25.387 -71.804,25.436 49.362,25.433 -2.395,25.562 -36.348,25.687 47.938,25.802 72.525,25.786 6.195,25.869 73.876,25.909 27.042,26.065 -3.108,26.078 -34.292,26.113 -32.192,26.113 -30.092,26.113 -27.992,26.113 -25.892,26.113 -23.792,26.113 -21.692,26.113 -19.592,26.113 -17.492,26.113 -15.392,26.113 -13.292,26.113 -11.192,26.113 -9.092,26.113 -6.992,26.113 75.676,26.123 59.213,26.229 2.038,26.316 66.338,26.344 -74.737,26.355 8.164,26.365 10.264,26.365 12.364,26.365 14.464,26.365 16.564,26.365 18.664,26.365 20.764,26.365 22.864,26.365 24.964,26.365 55.126,26.394 71.101,26.393 -4.739,26.462 63.838,26.475 53.373,26.655 65.262,26.74 3.462,26.801 57.189,26.788 60.659,26.799 -73.289,26.921 67.762,27.22 8.696,27.328 10.796,27.328 12.896,27.328 14.996,27.328 17.096,27.328 19.196,27.328 21.296,27.328 23.396,27.328 25.496,27.328 27.596,27.328 29.696,27.328 31.796,27.328 33.896,27.328 35.996,27.328 38.096,27.328 40.196,27.328 42.296,27.328 44.396,27.328 46.496,27.328 4.71,27.354 -35.336,27.537 -33.236,27.537 -31.136,27.537 -29.036,27.537 -26.936,27.537 -24.836,27.537 -22.736,27.537 -20.636,27.537 -18.536,27.537 -16.436,27.537 -14.336,27.537 -12.236,27.537 -10.136,27.537 -8.036,27.537 49.237,27.53 74.237,27.652 72.812,27.72 -5.948,27.765 6.641,27.76 54.885,28.113 -75.787,28.173 -14.75,28.163 -12.65,28.163 -10.55,28.163 -8.45,28.163 59.082,28.186 56.982,28.212 66.338,28.444 71.101,28.493 63.838,28.575 -74.363,28.726 9.73,28.753 11.83,28.753 13.93,28.753 16.03,28.753 18.13,28.753 20.23,28.753 22.33,28.753 24.43,28.753 26.53,28.753 28.63,28.753 30.73,28.753 32.83,28.753 34.93,28.753 39.13,28.753 41.23,28.753 43.33,28.753 45.43,28.753 47.53,28.753 7.63,28.785 -16.734,28.852 65.262,28.84 -60.798,29.238 -58.698,29.238 -56.598,29.238 -54.498,29.238 -52.398,29.238 -50.298,29.238 -48.198,29.238 -46.098,29.238 -43.998,29.238 -41.898,29.238 -39.798,29.238 -37.698,29.238 -35.598,29.238 -33.498,29.238 -31.398,29.238 -29.298,29.238 -27.198,29.238 -25.098,29.238 -22.998,29.238 -20.898,29.238 -18.798,29.238 67.762,29.32 -13.385,29.587 -11.285,29.587 -9.185,29.587 -7.085,29.587 8.285,29.578 10.385,29.578 12.485,29.578 14.585,29.578 16.685,29.578 18.785,29.578 -15.485,29.617 20.885,29.629 72.788,29.819 71.15,29.85 53.53,30.038 55.63,30.038 57.73,30.038 59.83,30.038 -13.759,30.214 -11.659,30.214 -9.559,30.214 -7.459,30.214 -75.787,30.273 -62.468,30.511 66.338,30.544 -59.306,30.662 -57.206,30.662 -55.106,30.662 -53.006,30.662 -50.906,30.662 -48.806,30.662 -46.706,30.662 -44.606,30.662 -42.506,30.662 -40.406,30.662 -38.306,30.662 -36.206,30.662 -34.106,30.662 -32.006,30.662 -29.906,30.662 -27.806,30.662 -25.706,30.662 -23.606,30.662 -21.506,30.662 -19.406,30.662 -17.306,30.662 63.838,30.675 -74.363,30.826 65.262,30.94 18.119,31.003 20.219,31.003 22.424,31.058 51.826,31.266 61.539,31.257 -61.291,31.348 24.502,31.363 26.602,31.363 28.702,31.363 30.802,31.363 32.902,31.363 37.102,31.363 39.202,31.363 41.302,31.363 43.402,31.363 67.762,31.42 9.839,31.453 11.939,31.453 14.039,31.453 16.139,31.453 55.135,31.462 57.235,31.462 59.335,31.462 -15.425,31.493 -11.536,31.639 -9.436,31.639 -13.635,31.717 7.762,31.764 -63.953,31.996 53.106,32.002 45.379,32.071 -75.787,32.373 21.77,32.418 17.985,32.453 -31.961,32.513 -29.861,32.513 -27.761,32.513 -25.661,32.513 -23.561,32.513 -21.461,32.513 -19.361,32.513 -17.261,32.513 66.338,32.644 61.004,32.737 23.838,32.787 25.938,32.787 28.038,32.787 30.138,32.787 32.238,32.787 34.338,32.787 36.438,32.787 38.538,32.787 40.638,32.787 42.738,32.787 63.838,32.775 -62.776,32.833 12.377,32.878 14.477,32.878 -74.363,32.926 62.662,33.032 65.262,33.04 16.57,33.052 -15.12,33.202 10.353,33.203 75.734,33.206 51.213,33.274 -13.124,33.363 44.733,33.441 -65.438,33.481 -33.829,33.472 -10.201,33.458 8.276,33.513 67.762,33.52 46.864,33.556 12.381,33.748 -31.787,33.937 -29.687,33.937 -27.587,33.937 -25.487,33.937 -21.287,33.937 -17.087,33.937 19.47,33.938 -64.261,34.318 -75.118,34.364 -12.101,34.354 -72.97,34.498 18.055,34.537 -9.81,34.679 77.206,34.704 63.838,34.875 8.75,34.9 11.325,34.9 46.218,34.926 48.349,35.041 62.662,35.132 -33.498,35.155 65.262,35.14 13.866,35.233 50.44,35.227 -7.575,35.25 75.818,35.304 6.7,35.325 -29.245,35.363 -27.145,35.363 -25.045,35.363 -22.945,35.363 -20.845,35.363 -18.745,35.363 -16.645,35.363 -71.076,35.406 -68.976,35.406 20.955,35.423 23.055,35.463 25.155,35.463 27.255,35.463 29.355,35.463 31.455,35.463 33.555,35.463 35.655,35.463 37.755,35.463 39.855,35.463 41.955,35.463 -56.232,35.538 -54.132,35.538 -52.032,35.538 -49.932,35.538 -47.832,35.538 -45.732,35.538 -43.632,35.538 -41.532,35.538 -39.432,35.538 -58.327,35.678 -65.746,35.803 -13.586,35.839 -73.634,35.849 -9.052,35.936 51.737,35.946 19.54,36.022 -11.295,36.164 43.931,36.174 67.964,36.2 5.806,36.237 70.036,36.241 -31.066,36.409 47.703,36.411 49.782,36.712 -28.059,36.787 -25.959,36.787 -23.859,36.787 -21.759,36.787 -19.659,36.787 -17.559,36.787 -15.459,36.787 77.362,36.798 -71.777,36.83 -69.677,36.83 -67.577,36.83 21.454,36.887 23.554,36.887 25.654,36.887 27.754,36.887 29.854,36.887 31.954,36.887 34.054,36.887 36.154,36.887 38.254,36.887 40.354,36.887 42.454,36.887 12.713,36.919 61.238,36.924 -55.958,36.962 -53.858,36.962 -51.758,36.962 -49.658,36.962 -47.558,36.962 -45.458,36.962 -43.358,36.962 -39.158,36.962 63.838,36.975 -5.729,37.004 -59.829,37.146 -7.903,37.163 71.144,37.188 65.262,37.24 14.137,37.316 -58.021,37.353 75.938,37.401 -30.062,37.419 -10.537,37.421 45.416,37.659 -12.312,38.001 6.812,38.08 5.388,38.129 11.039,38.188 44.024,38.281 47.403,38.338 49.503,38.338 51.603,38.338 53.703,38.338 55.803,38.338 -4.163,38.49 57.886,38.604 -61.314,38.631 -6.888,38.756 -59.506,38.838 -31.547,38.904 77.362,38.898 28.266,39.013 30.366,39.026 61.238,39.024 63.838,39.075 9.146,39.097 13.047,39.11 -8.312,39.223 4.025,39.309 62.662,39.332 65.262,39.34 -10.888,39.491 75.938,39.501 11.008,39.612 45.563,39.71 47.662,39.762 49.762,39.762 51.862,39.762 53.962,39.762 56.062,39.762 -12.312,40.101 -62.799,40.116 -28.258,40.163 -26.158,40.163 -24.058,40.163 -21.958,40.163 6.812,40.18 5.388,40.229 26.59,40.278 59.162,40.271 -60.991,40.323 -33.032,40.389 -1.639,40.39 31.967,40.385 -19.874,40.419 68.3,40.425 30.037,40.47 -4.259,40.553 73.15,40.575 -6.129,40.714 66.83,40.738 -35.521,40.863 27.982,40.9 77.362,40.998 57.738,41.028 75.3,41.05 33.955,41.063 36.055,41.063 38.155,41.063 40.255,41.063 42.355,41.063 8.513,41.099 61.238,41.124 64.231,41.138 -7.644,41.214 62.662,41.432 9.971,41.438 -29.891,41.484 -64.284,41.601 -26.663,41.587 -24.563,41.587 -22.463,41.587 -10.888,41.591 75.938,41.601 44.368,41.661 -62.476,41.808 -34.517,41.874 -18.389,41.904 -20.39,41.918 31.522,41.955 25.363,41.982 11.976,42.063 14.076,42.063 16.176,42.063 18.276,42.063 66.064,42.162 -12.312,42.201 -0.787,42.217 20.371,42.2 -28.653,42.26 6.812,42.28 5.388,42.329 53.996,42.338 56.096,42.338 -37.006,42.348 51.896,42.368 58.996,42.365 72.4,42.35 4.069,42.408 -4.963,42.46 33.554,42.487 35.653,42.487 37.753,42.487 39.853,42.487 41.953,42.487 68.329,42.492 26.787,42.628 -6.387,42.896 -31.376,42.968 9.48,42.963 65,43 -65.768,43.086 77.362,43.098 43.919,43.226 61.238,43.224 73.898,43.227 -63.961,43.293 -36.002,43.359 45.562,43.388 -18.905,43.403 0.637,43.47 11.514,43.487 13.614,43.487 15.714,43.487 17.814,43.487 62.662,43.532 21.874,43.667 -17.288,43.692 -10.888,43.691 19.902,43.709 75.938,43.701 -30.138,43.745 50.328,43.765 53.213,43.762 55.313,43.762 57.413,43.745 66.775,43.75 72.475,43.775 -38.491,43.833 25.363,44.082 -12.312,44.301 -0.787,44.317 6.812,44.38 5.388,44.429 -32.861,44.453 -67.253,44.571 -4.963,44.56 26.787,44.728 51.359,44.748 -65.445,44.778 -37.487,44.844 -6.387,44.996 65,45 77.362,45.198 -31.623,45.23 21.338,45.242 48.843,45.25 -39.976,45.318 43.57,45.297 61.238,45.324 45.386,45.48 4.069,45.508 0.637,45.57 22.762,45.569 31,45.647 33.1,45.647 35.2,45.647 37.3,45.647 39.4,45.647 41.5,45.647 62.662,45.632 -54.012,45.691 18.484,45.763 -10.888,45.791 53.476,45.792 75.938,45.801 -34.346,45.938 -18.863,46.009 -17.113,46.009 -68.721,46.073 54.925,46.075 17.009,46.113 25.363,46.182 49.874,46.233 -66.93,46.263 13.81,46.288 15.91,46.288 -38.971,46.329 -12.312,46.401 -0.787,46.417 6.812,46.48 -55.237,46.516 -52.787,46.516 5.388,46.529 -4.963,46.66 -33.108,46.715 47.358,46.735 -41.461,46.803 26.787,46.827 29.352,46.95 43.887,46.951 19.309,46.988 65,47 31.291,47.072 33.391,47.072 35.491,47.072 37.591,47.072 39.691,47.072 41.791,47.072 52.68,47.082 -6.387,47.096 11.886,47.131 60.277,47.191 77.362,47.298 21.338,47.342 -35.831,47.423 -19.213,47.484 -16.763,47.484 55.208,47.524 61.896,47.587 0.637,47.67 22.801,47.669 15.353,47.712 13.254,47.779 48.45,47.776 -40.413,47.856 17.009,47.863 -11.018,47.887 52.098,47.894 75.938,47.901 -54.887,47.991 -53.137,47.991 -68.862,48.168 -34.592,48.2 18.484,48.213 24.83,48.213 -13.34,48.232 -67.438,48.301 -17.988,48.309 53.918,48.32 -0.787,48.517 6.812,48.58 -54.712,48.603 4.069,48.608 10.402,48.616 5.388,48.629 58.792,48.676 -4.963,48.76 47.025,48.808 26.211,48.847 -41.837,48.869 30.337,48.943 65,49 28.913,49.003 60.411,49.072 -53.288,49.16 -6.387,49.196 22.317,49.199 11.769,49.264 -36.637,49.362 -12.484,49.391 77.362,49.398 52.837,49.411 -25.377,49.663 -23.277,49.663 -21.177,49.663 -19.077,49.663 -16.977,49.663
